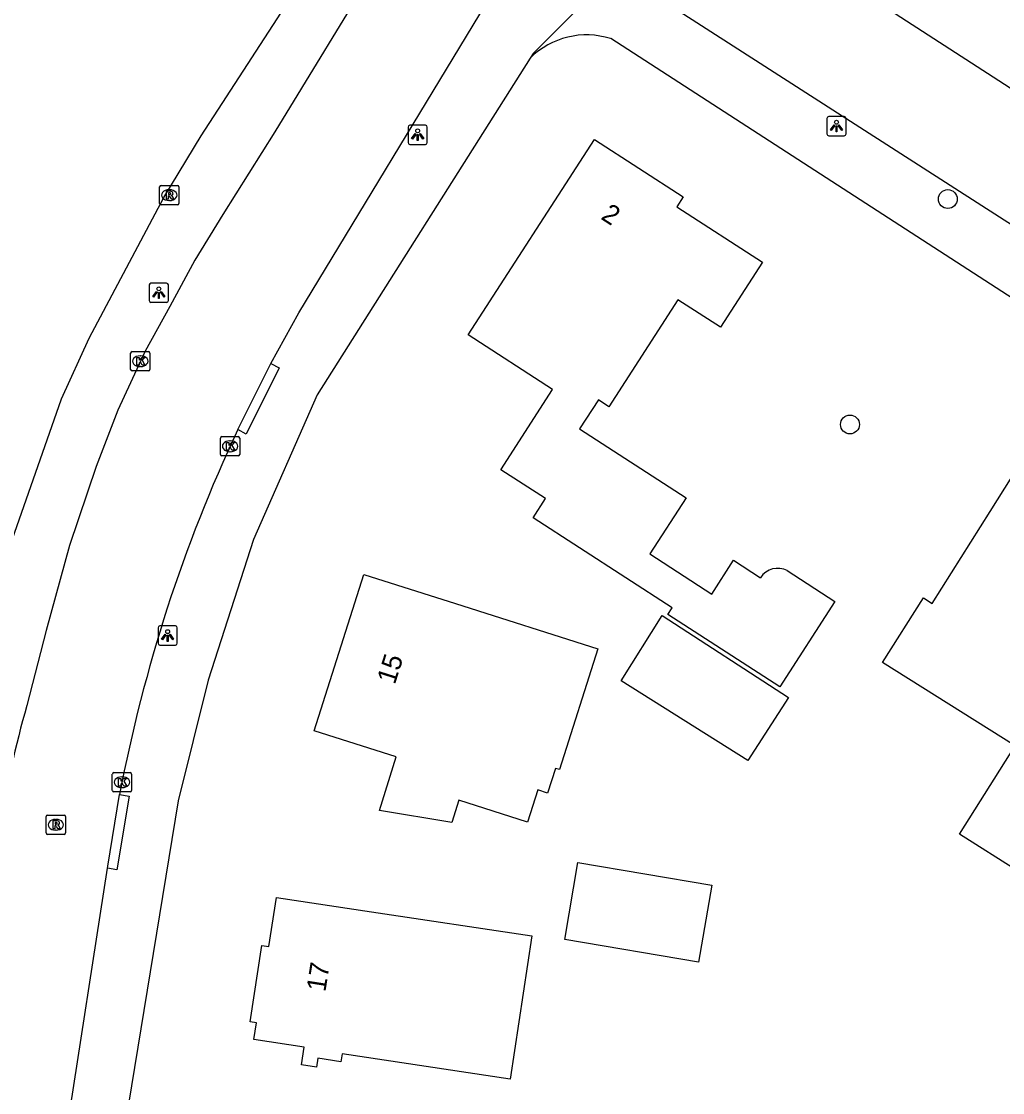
# Model space of a CAD drawing. Extents: x 161141 to 161601, y 381708 to 382245.
# Drawn here: x 161275.5 to 161326.4, y 382019.7 to 382075.2 of the extents above; entities that cross this region are included whole.
import ezdxf

# ---------------------------------------------------------------- set-up
doc = ezdxf.new("R2010")
doc.units = 0
for name, color, linetype in [('IMGEO_Boom', 7, 'Continuous'), ('IMGEO_Kolk', 7, 'Continuous'), ('IMGEO_Lichtpunt', 7, 'Continuous'), ('IMGEO_Pand', 7, 'Continuous'), ('IMGEO_Pand_nummerreeks', 7, 'Continuous'), ('IMGEO_Rijbaan_lokaal_open', 7, 'Continuous'), ('IMGEO_Rioolput', 7, 'Continuous'), ('IMGEO_Voetpad_open', 7, 'Continuous')]:
    doc.layers.add(name, color=color, linetype=linetype)

msp = doc.modelspace()

# ---------------------------------------------------------------- linework, layer by layer
at = {"layer": 'IMGEO_Boom'}
for centre in [(161323.56, 382066.027), (161318.485, 382054.336)]:
    msp.add_circle(centre, 0.489, dxfattribs=at)
at = {"layer": 'IMGEO_Kolk'}
for p, q in [((161281.155, 382057.187), (161281.155, 382058.039)), ((161281.23, 382058.113), (161282.082, 382058.113)), ((161281.643, 382057.893), (161281.668, 382057.893)), ((161282.156, 382058.039), (161282.156, 382057.187)), ((161281.666, 382057.333), (161281.641, 382057.333)), ((161282.082, 382057.113), (161281.23, 382057.113)), ((161285.815, 382052.777), (161285.815, 382053.629)), ((161285.89, 382053.703), (161286.742, 382053.703)), ((161286.303, 382053.483), (161286.328, 382053.483)), ((161286.816, 382053.629), (161286.816, 382052.777)), ((161286.326, 382052.923), (161286.301, 382052.923)), ((161286.742, 382052.703), (161285.89, 382052.703)), ((161280.205, 382035.352), (161280.205, 382036.204)), ((161280.28, 382036.278), (161281.132, 382036.278)), ((161281.206, 382036.204), (161281.206, 382035.352)), ((161280.693, 382036.058), (161280.718, 382036.058)), ((161281.132, 382035.278), (161280.28, 382035.278)), ((161280.716, 382035.498), (161280.691, 382035.498))]:
    msp.add_line(p, q, dxfattribs=at)
for points in [[(161281.155, 382057.187), (161281.155, 382058.039)], [(161281.23, 382058.113), (161282.082, 382058.113)], [(161281.476, 382057.813), (161281.599, 382057.813), (161281.599, 382057.662), (161281.729, 382057.813), (161281.893, 382057.813), (161281.747, 382057.662), (161281.9, 382057.413), (161281.748, 382057.413), (161281.663, 382057.577), (161281.599, 382057.51), (161281.599, 382057.413), (161281.476, 382057.413), (161281.476, 382057.813)], [(161282.156, 382058.039), (161282.156, 382057.187)], [(161282.082, 382057.113), (161281.23, 382057.113)], [(161285.815, 382052.777), (161285.815, 382053.629)], [(161285.89, 382053.703), (161286.742, 382053.703)], [(161286.136, 382053.403), (161286.259, 382053.403), (161286.259, 382053.252), (161286.389, 382053.403), (161286.553, 382053.403), (161286.407, 382053.252), (161286.56, 382053.003), (161286.408, 382053.003), (161286.323, 382053.167), (161286.259, 382053.1), (161286.259, 382053.003), (161286.136, 382053.003), (161286.136, 382053.403)], [(161286.816, 382053.629), (161286.816, 382052.777)], [(161286.742, 382052.703), (161285.89, 382052.703)], [(161280.205, 382035.352), (161280.205, 382036.204)], [(161280.28, 382036.278), (161281.132, 382036.278)], [(161281.206, 382036.204), (161281.206, 382035.352)], [(161280.526, 382035.978), (161280.649, 382035.978), (161280.649, 382035.827), (161280.779, 382035.978), (161280.943, 382035.978), (161280.797, 382035.827), (161280.95, 382035.578), (161280.798, 382035.578), (161280.713, 382035.742), (161280.649, 382035.675), (161280.649, 382035.578), (161280.526, 382035.578), (161280.526, 382035.978)], [(161281.132, 382035.278), (161280.28, 382035.278)]]:
    msp.add_lwpolyline(points, dxfattribs=at)
for centre, start, end in [((161281.232, 382058.037), 91.552, 178.448), ((161281.232, 382058.037), 91.552, 178.448), ((161282.08, 382058.037), 1.552, 88.448), ((161282.08, 382058.037), 1.552, 88.448), ((161281.232, 382057.189), 181.552, 268.448), ((161281.232, 382057.189), 181.552, 268.448), ((161282.08, 382057.189), 271.552, 358.448), ((161282.08, 382057.189), 271.552, 358.448), ((161285.892, 382053.627), 91.552, 178.448), ((161285.892, 382053.627), 91.552, 178.448), ((161286.74, 382053.627), 1.552, 88.448), ((161286.74, 382053.627), 1.552, 88.448), ((161285.892, 382052.779), 181.552, 268.448), ((161285.892, 382052.779), 181.552, 268.448), ((161286.74, 382052.779), 271.552, 358.448), ((161286.74, 382052.779), 271.552, 358.448), ((161280.282, 382036.202), 91.552, 178.448), ((161280.282, 382036.202), 91.552, 178.448), ((161281.13, 382036.202), 1.552, 88.448), ((161281.13, 382036.202), 1.552, 88.448), ((161280.282, 382035.354), 181.552, 268.448), ((161280.282, 382035.354), 181.552, 268.448), ((161281.13, 382035.354), 271.552, 358.448), ((161281.13, 382035.354), 271.552, 358.448)]:
    msp.add_arc(centre, 0.0765, start, end, dxfattribs=at)
for centre, major_axis, ratio, start_param, end_param in [((161281.642, 382057.613), (-0.387, 0.002), 0.722429, 4.712389, 7.853982), ((161281.667, 382057.613), (-0.39, 0.002), 0.717154, 1.570796, 4.712389), ((161286.302, 382053.203), (-0.387, 0.002), 0.722429, 4.712389, 7.853982), ((161286.327, 382053.203), (-0.39, 0.002), 0.717154, 1.570796, 4.712389), ((161280.692, 382035.778), (-0.387, 0.002), 0.722429, 4.712389, 7.853982), ((161280.717, 382035.778), (-0.39, 0.002), 0.717154, 1.570796, 4.712389)]:
    msp.add_ellipse(centre, major_axis=major_axis, ratio=ratio, start_param=start_param, end_param=end_param, dxfattribs=at)
at = {"layer": 'IMGEO_Lichtpunt'}
for p, q in [((161317.286, 382070.213), (161317.286, 382069.406)), ((161317.286, 382070.213), (161317.286, 382069.406)), ((161318.188, 382070.308), (161317.38, 382070.308)), ((161318.188, 382070.308), (161317.38, 382070.308)), ((161318.282, 382069.406), (161318.282, 382070.213)), ((161318.282, 382069.406), (161318.282, 382070.213)), ((161295.551, 382069.764), (161295.551, 382068.957)), ((161295.551, 382069.764), (161295.551, 382068.957)), ((161296.453, 382069.859), (161295.645, 382069.859)), ((161296.453, 382069.859), (161295.645, 382069.859)), ((161296.547, 382068.957), (161296.547, 382069.764)), ((161296.547, 382068.957), (161296.547, 382069.764)), ((161317.38, 382069.312), (161318.188, 382069.312)), ((161317.38, 382069.312), (161318.188, 382069.312)), ((161295.645, 382068.863), (161296.453, 382068.863)), ((161295.645, 382068.863), (161296.453, 382068.863)), ((161283.019, 382061.666), (161282.211, 382061.666)), ((161283.019, 382061.666), (161282.211, 382061.666)), ((161282.117, 382061.571), (161282.117, 382060.764)), ((161282.117, 382061.571), (161282.117, 382060.764)), ((161283.113, 382060.764), (161283.113, 382061.571)), ((161283.113, 382060.764), (161283.113, 382061.571)), ((161282.211, 382060.67), (161283.019, 382060.67)), ((161282.211, 382060.67), (161283.019, 382060.67)), ((161283.479, 382043.886), (161282.671, 382043.886)), ((161283.479, 382043.886), (161282.671, 382043.886)), ((161282.577, 382043.791), (161282.577, 382042.984)), ((161282.577, 382043.791), (161282.577, 382042.984)), ((161283.573, 382042.984), (161283.573, 382043.791)), ((161283.573, 382042.984), (161283.573, 382043.791)), ((161282.671, 382042.89), (161283.479, 382042.89)), ((161282.671, 382042.89), (161283.479, 382042.89))]:
    msp.add_line(p, q, dxfattribs=at)
for points in [[(161295.925, 382069.428), (161295.964, 382069.4), (161295.776, 382069.138), (161295.738, 382069.165), (161295.925, 382069.428)], [(161296.137, 382069.4), (161296.175, 382069.427), (161296.362, 382069.165), (161296.323, 382069.137), (161296.137, 382069.4)], [(161317.66, 382069.877), (161317.699, 382069.849), (161317.511, 382069.587), (161317.473, 382069.614), (161317.66, 382069.877)], [(161317.762, 382069.829), (161317.809, 382069.829), (161317.809, 382069.507), (161317.762, 382069.507), (161317.762, 382069.829)], [(161317.872, 382069.849), (161317.91, 382069.876), (161318.097, 382069.614), (161318.058, 382069.586), (161317.872, 382069.849)], [(161296.027, 382069.38), (161296.074, 382069.38), (161296.074, 382069.058), (161296.027, 382069.058), (161296.027, 382069.38)], [(161282.491, 382061.235), (161282.53, 382061.207), (161282.342, 382060.945), (161282.304, 382060.972), (161282.491, 382061.235)], [(161282.593, 382061.187), (161282.64, 382061.187), (161282.64, 382060.865), (161282.593, 382060.865), (161282.593, 382061.187)], [(161282.703, 382061.207), (161282.741, 382061.234), (161282.928, 382060.972), (161282.889, 382060.944), (161282.703, 382061.207)], [(161282.951, 382043.455), (161282.99, 382043.427), (161282.802, 382043.165), (161282.764, 382043.192), (161282.951, 382043.455)], [(161283.053, 382043.407), (161283.1, 382043.407), (161283.1, 382043.085), (161283.053, 382043.085), (161283.053, 382043.407)], [(161283.163, 382043.427), (161283.201, 382043.454), (161283.388, 382043.192), (161283.349, 382043.164), (161283.163, 382043.427)]]:
    msp.add_lwpolyline(points, dxfattribs=at)
for centre in [(161317.785, 382070.011), (161296.05, 382069.562), (161282.616, 382061.369), (161283.076, 382043.589)]:
    msp.add_circle(centre, 0.0994, dxfattribs=at)
for centre, start, end in [((161317.38, 382070.213), 90, 180), ((161317.38, 382070.213), 90, 180), ((161318.188, 382070.213), 0, 90), ((161318.188, 382070.213), 0, 90), ((161295.645, 382069.764), 90, 180), ((161295.645, 382069.764), 90, 180), ((161296.453, 382069.764), 0, 90), ((161296.453, 382069.764), 0, 90), ((161295.645, 382068.957), 180, 270), ((161295.645, 382068.957), 180, 270), ((161296.453, 382068.957), 270, 0), ((161296.453, 382068.957), 270, 360), ((161317.38, 382069.406), 180, 270), ((161317.38, 382069.406), 180, 270), ((161318.188, 382069.406), 270, 0), ((161318.188, 382069.406), 270, 360), ((161282.211, 382061.571), 90, 180), ((161282.211, 382061.571), 90, 180), ((161283.019, 382061.571), 0, 90), ((161283.019, 382061.571), 0, 90), ((161282.211, 382060.764), 180, 270), ((161282.211, 382060.764), 180, 270), ((161283.019, 382060.764), 270, 0), ((161283.019, 382060.764), 270, 360), ((161282.671, 382043.791), 90, 180), ((161282.671, 382043.791), 90, 180), ((161283.479, 382043.791), 0, 90), ((161283.479, 382043.791), 0, 90), ((161282.671, 382042.984), 180, 270), ((161282.671, 382042.984), 180, 270), ((161283.479, 382042.984), 270, 0), ((161283.479, 382042.984), 270, 360)]:
    msp.add_arc(centre, 0.0946, start, end, dxfattribs=at)
at = {"layer": 'IMGEO_Pand'}
for points in [[(161302.036, 382049.498), (161302.677, 382050.489), (161300.358, 382051.989), (161303.045, 382056.146), (161298.669, 382058.976), (161305.221, 382069.111), (161309.823, 382066.136), (161309.493, 382065.626), (161313.942, 382062.75), (161311.764, 382059.381), (161309.556, 382060.808), (161305.969, 382055.257), (161305.428, 382055.607), (161304.454, 382054.101), (161309.98, 382050.528), (161308.099, 382047.617), (161311.312, 382045.54), (161312.444, 382047.29), (161313.843, 382046.386)], [(161327.227, 382031.156), (161324.172, 382033.077), (161327.053, 382037.661), (161320.18, 382041.981), (161322.293, 382045.342), (161322.758, 382045.049), (161325.756, 382049.819), (161328.417, 382054.052), (161329.525, 382053.356), (161330.221, 382053.724), (161332.458, 382052.318), (161332.427, 382051.481), (161335.761, 382049.386), (161329.259, 382039.042), (161331.435, 382037.66)], [(161315.233, 382046.758), (161317.706, 382045.158), (161314.844, 382040.73), (161309.038, 382044.479), (161309.262, 382044.827), (161302.036, 382049.498)], [(161303.197, 382036.497), (161302.791, 382035.219), (161302.289, 382035.386), (161301.757, 382033.71), (161298.19, 382034.841), (161297.826, 382033.694), (161294.062, 382034.318), (161294.942, 382037.087), (161290.672, 382038.443), (161293.249, 382046.556), (161298.015, 382045.043), (161305.396, 382042.699), (161303.406, 382036.431), (161303.197, 382036.497)], [(161306.609, 382041.036), (161308.737, 382044.423), (161315.296, 382040.174), (161313.181, 382036.907), (161306.609, 382041.036)], [(161310.629, 382026.444), (161303.689, 382027.624), (161304.368, 382031.618), (161311.308, 382030.438), (161310.629, 382026.444)], [(161290.014, 382021.115), (161290.153, 382022.036), (161287.554, 382022.426), (161287.686, 382023.3), (161287.362, 382023.349), (161287.957, 382027.313), (161288.335, 382027.257), (161288.717, 382029.8), (161293.662, 382029.057), (161301.968, 382027.808), (161300.853, 382020.383), (161292.13, 382021.693), (161292.068, 382021.281), (161290.868, 382021.462), (161290.798, 382020.998), (161290.014, 382021.115)]]:
    msp.add_lwpolyline(points, dxfattribs=at)
msp.add_arc((161314.743, 382045.806), 1.07, 62.7483, 147.2171, dxfattribs=at)
at = {"layer": 'IMGEO_Rijbaan_lokaal_open'}
for points in [[(161311.536, 382081.664), (161356.674, 382052.498), (161362.411, 382048.813), (161375.585, 382040.285), (161382.572, 382035.748), (161395.928, 382027.083), (161402.927, 382022.535), (161416.852, 382013.552), (161420.042, 382011.494), (161421.741, 382010.379), (161425.551, 382007.922), (161458.647, 381986.439), (161460.91, 381984.988)], [(161294.185, 382078.667), (161293.982, 382078.282), (161288.638, 382069.521), (161285.944, 382065.234), (161284.484, 382062.864), (161283.194, 382060.455), (161281.902, 382058.145), (161280.487, 382055.075), (161279.36, 382052.147), (161277.983, 382048.057), (161276.769, 382043.649), (161275.765, 382039.756)], [(161480.897, 381964.849), (161471.977, 381970.646), (161450.889, 381984.377), (161443.856, 381988.93), (161430.314, 381997.713), (161423.318, 382002.239), (161408.287, 382012.005), (161402.555, 382015.697), (161398.439, 382018.395), (161388.068, 382025.069), (161381.679, 382029.228), (161366.307, 382039.161), (161359.944, 382043.32), (161345.442, 382052.667), (161339.032, 382056.795), (161328.504, 382063.628), (161325.321, 382065.668), (161306.338, 382077.878)], [(161288.423, 382057.491), (161289.88, 382060.122), (161299.28, 382075.613), (161300.362, 382077.308)], [(161286.714, 382054.067), (161288.423, 382057.491)], [(161279.948, 382031.313), (161279.965, 382031.42), (161280.583, 382035.146)], [(161275.698, 382003.858), (161279.948, 382031.313)]]:
    msp.add_lwpolyline(points, dxfattribs=at)
for centre, radius, start, end in [((161358.746, 382020.273), 79.565, 154.86594, 169.22614), ((161342.19, 382021.244), 68.956, 164.42712, 169.83954)]:
    msp.add_arc(centre, radius, start, end, dxfattribs=at)
at = {"layer": 'IMGEO_Rioolput'}
for p, q in [((161282.66, 382065.804), (161282.66, 382066.656)), ((161282.735, 382066.73), (161283.587, 382066.73)), ((161283.661, 382066.656), (161283.661, 382065.804)), ((161283.148, 382066.51), (161283.173, 382066.51)), ((161283.587, 382065.73), (161282.735, 382065.73)), ((161283.171, 382065.95), (161283.146, 382065.95)), ((161276.773, 382033.146), (161276.773, 382033.998)), ((161276.848, 382034.072), (161277.7, 382034.072)), ((161277.774, 382033.998), (161277.774, 382033.146)), ((161277.261, 382033.852), (161277.286, 382033.852)), ((161277.7, 382033.072), (161276.848, 382033.072)), ((161277.284, 382033.292), (161277.259, 382033.292))]:
    msp.add_line(p, q, dxfattribs=at)
for points in [[(161282.66, 382065.804), (161282.66, 382066.656)], [(161282.735, 382066.73), (161283.587, 382066.73)], [(161283.661, 382066.656), (161283.661, 382065.804)], [(161283.249, 382066.428), (161282.997, 382066.43), (161282.997, 382066.03)], [(161282.997, 382066.03), (161283.121, 382066.03), (161283.121, 382066.192), (161283.132, 382066.192)], [(161283.175, 382066.349), (161283.121, 382066.349), (161283.121, 382066.268)], [(161283.121, 382066.268), (161283.173, 382066.268)], [(161283.179, 382066.163), (161283.25, 382066.03), (161283.39, 382066.03), (161283.325, 382066.156)], [(161283.587, 382065.73), (161282.735, 382065.73)], [(161276.773, 382033.146), (161276.773, 382033.998)], [(161276.848, 382034.072), (161277.7, 382034.072)], [(161277.774, 382033.998), (161277.774, 382033.146)], [(161277.362, 382033.77), (161277.11, 382033.772), (161277.11, 382033.372)], [(161277.11, 382033.372), (161277.234, 382033.372), (161277.234, 382033.534), (161277.245, 382033.534)], [(161277.288, 382033.691), (161277.234, 382033.691), (161277.234, 382033.61)], [(161277.234, 382033.61), (161277.286, 382033.61)], [(161277.292, 382033.505), (161277.363, 382033.372), (161277.503, 382033.372), (161277.438, 382033.498)], [(161277.7, 382033.072), (161276.848, 382033.072)]]:
    msp.add_lwpolyline(points, dxfattribs=at)
for centre, radius, start, end in [((161282.737, 382066.654), 0.0765, 91.552, 178.448), ((161282.737, 382066.654), 0.0765, 91.552, 178.448), ((161283.585, 382066.654), 0.0765, 1.552, 88.448), ((161283.585, 382066.654), 0.0765, 1.552, 88.448), ((161283.131, 382066.139), 0.0533, 26.0293, 88.6989), ((161283.157, 382066.457), 0.19, 274.7715, 282.9687), ((161283.181, 382066.253), 0.0964, 77.0061, 93.1865), ((161283.195, 382066.31), 0.0378, 276.6634, 79.6772), ((161283.248, 382066.318), 0.109, 350.3612, 89.416), ((161283.246, 382066.318), 0.112, 277.5842, 350.9817), ((161283.23, 382066.103), 0.108, 29.5134, 73.7905), ((161282.737, 382065.806), 0.0765, 181.552, 268.448), ((161282.737, 382065.806), 0.0765, 181.552, 268.448), ((161283.585, 382065.806), 0.0765, 271.552, 358.448), ((161283.585, 382065.806), 0.0765, 271.552, 358.448), ((161276.85, 382033.996), 0.0765, 91.552, 178.448), ((161276.85, 382033.996), 0.0765, 91.552, 178.448), ((161277.698, 382033.996), 0.0765, 1.552, 88.448), ((161277.698, 382033.996), 0.0765, 1.552, 88.448), ((161277.244, 382033.481), 0.0533, 26.0293, 88.6989), ((161277.27, 382033.799), 0.19, 274.7715, 282.9687), ((161277.294, 382033.595), 0.0964, 77.0061, 93.1865), ((161277.308, 382033.652), 0.0378, 276.6634, 79.6772), ((161277.361, 382033.66), 0.109, 350.3612, 89.416), ((161277.359, 382033.66), 0.112, 277.5842, 350.9817), ((161277.343, 382033.445), 0.108, 29.5134, 73.7905), ((161276.85, 382033.148), 0.0765, 181.552, 268.448), ((161276.85, 382033.148), 0.0765, 181.552, 268.448), ((161277.698, 382033.148), 0.0765, 271.552, 358.448), ((161277.698, 382033.148), 0.0765, 271.552, 358.448)]:
    msp.add_arc(centre, radius, start, end, dxfattribs=at)
for centre, major_axis, ratio, start_param, end_param in [((161283.147, 382066.23), (-0.387, 0.002), 0.722429, 4.712389, 7.853982), ((161283.172, 382066.23), (-0.39, 0.002), 0.717154, 1.570796, 4.712389), ((161277.26, 382033.572), (-0.387, 0.002), 0.722429, 4.712389, 7.853982), ((161277.285, 382033.572), (-0.39, 0.002), 0.717154, 1.570796, 4.712389)]:
    msp.add_ellipse(centre, major_axis=major_axis, ratio=ratio, start_param=start_param, end_param=end_param, dxfattribs=at)
at = {"layer": 'IMGEO_Voetpad_open'}
for points in [[(161274.272, 382046.274), (161277.573, 382055.662), (161279.007, 382058.811), (161282.872, 382066.104), (161284.809, 382069.306), (161291.381, 382079.434)], [(161306.338, 382077.878), (161302.036, 382073.583), (161301.893, 382073.339)], [(161474.804, 381965.241), (161421.048, 382000), (161306.066, 382074.349)], [(161301.893, 382073.339), (161290.838, 382055.877), (161287.538, 382048.363), (161285.187, 382041.077), (161283.628, 382034.817), (161278.294, 382002.287)], [(161288.423, 382057.491), (161288.868, 382057.264), (161287.159, 382053.84), (161286.714, 382054.067)], [(161280.583, 382035.146), (161281.075, 382035.061), (161280.44, 382031.228), (161279.948, 382031.313)]]:
    msp.add_lwpolyline(points, dxfattribs=at)
msp.add_arc((161304.814, 382070.394), 4.148, 72.4386, 134.7729, dxfattribs=at)

# ---------------------------------------------------------------- texts
at = {"layer": 'IMGEO_Pand_nummerreeks'}
for s, rotation, p in [('2', 327.118, (161305.51, 382065.02)), ('15', 72.376, (161294.863, 382040.806)), ('17', 81.0392, (161291.26, 382024.876))]:
    msp.add_text(s, height=1, rotation=rotation, dxfattribs=at).set_placement(p)

doc.saveas('drawing.dxf')
